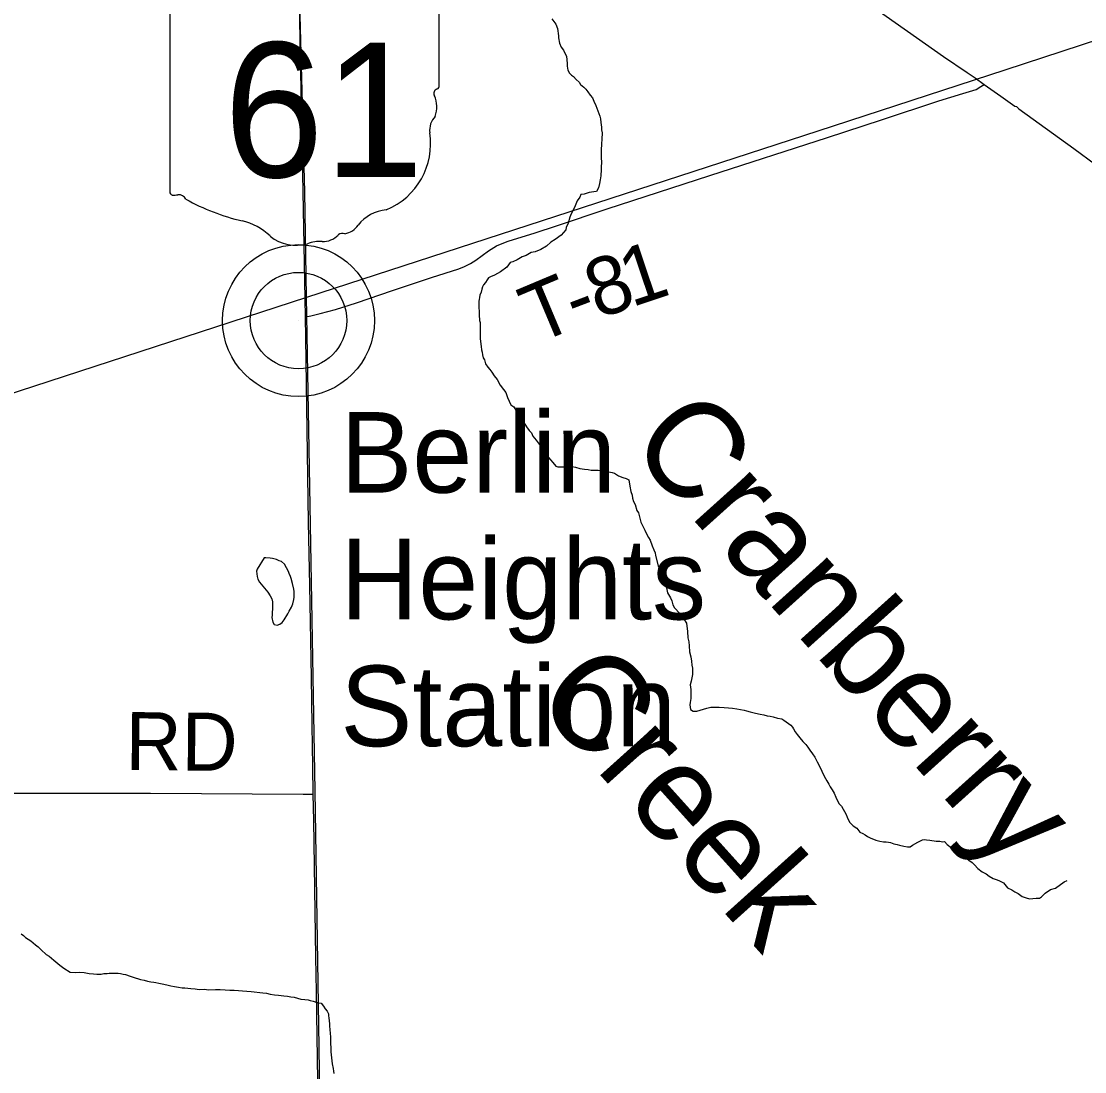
# Model space of a CAD drawing. Extents: x 0 to 34, y 0 to 22.
# Drawn here: x 6.721 to 7.762, y 15.772 to 16.8 of the extents above; entities that cross this region are included whole.
import ezdxf

# ---------------------------------------------------------------- set-up
doc = ezdxf.new("R2010")
doc.units = 0
for name, color, linetype in [('GM_X_Minor_Lake', 7, 'Continuous'), ('GM_X_Minor_River', 7, 'Continuous'), ('GM_X_Minor_River_Text', 7, 'Continuous'), ('GM_X_Rail_Line', 7, 'Continuous'), ('GM_X_State_Location', 7, 'Continuous'), ('GM_X_State_Route', 7, 'Continuous'), ('GM_X_State_Shield', 7, 'Continuous'), ('GM_X_Township_Road', 7, 'Continuous'), ('GM_X_Township_Road_Text', 7, 'Continuous'), ('GM_X_Unincorporated', 7, 'Continuous'), ('GM_X_Unincorporated_Location', 7, 'Continuous'), ('GM_X_Unincorporated_Text', 7, 'Continuous')]:
    doc.layers.add(name, color=color, linetype=linetype)

msp = doc.modelspace()

# ---------------------------------------------------------------- linework, layer by layer
at = {"layer": 'GM_X_Minor_Lake'}
for points in [[(6.9588, 16.2751), (6.9517, 16.264), (6.9513, 16.2621), (6.9518, 16.2568), (6.9526, 16.2541), (6.9541, 16.2511), (6.9574, 16.2471)], [(6.9574, 16.2471), (6.9622, 16.2413), (6.9645, 16.2379), (6.9661, 16.2348), (6.9669, 16.2318), (6.9669, 16.2265), (6.9669, 16.2246), (6.9666, 16.2219), (6.9666, 16.2189), (6.9662, 16.2166), (6.967, 16.212), (6.9686, 16.2098), (6.9713, 16.209), (6.9739, 16.2102), (6.9762, 16.2117), (6.9781, 16.2144), (6.9818, 16.2202), (6.9833, 16.2229), (6.9855, 16.2267), (6.9866, 16.2301), (6.9877, 16.2343), (6.9881, 16.2366), (6.988, 16.2419), (6.9876, 16.2442), (6.9864, 16.2499), (6.9852, 16.2548), (6.9845, 16.2567), (6.9833, 16.2598), (6.9825, 16.2617), (6.9786, 16.2688), (6.9756, 16.2715), (6.9733, 16.2722), (6.9706, 16.2733), (6.9668, 16.2744), (6.9645, 16.2748), (6.9603, 16.2751), (6.9592, 16.2751), (6.9588, 16.2751)]]:
    msp.add_lwpolyline(points, dxfattribs=at)
at = {"layer": 'GM_X_Minor_River'}
for points in [[(7.2405, 16.8028), (7.2444, 16.7975), (7.2459, 16.7934), (7.2468, 16.7861), (7.2468, 16.7842), (7.248, 16.7789), (7.2495, 16.7751), (7.2519, 16.7721), (7.2534, 16.7687), (7.2546, 16.7661), (7.2554, 16.7592), (7.2554, 16.7565), (7.2559, 16.7527), (7.2578, 16.7497), (7.2597, 16.7478), (7.2616, 16.7463), (7.2643, 16.7433), (7.267, 16.7407), (7.2685, 16.7384), (7.2716, 16.7358), (7.2735, 16.7339), (7.2755, 16.7313), (7.2778, 16.7282), (7.2801, 16.7256), (7.2816, 16.7222), (7.2836, 16.718), (7.2875, 16.7074), (7.2879, 16.7048), (7.2883, 16.7013), (7.2891, 16.6968), (7.2891, 16.6941), (7.2895, 16.6911), (7.2892, 16.685), (7.2889, 16.6804), (7.2886, 16.6743), (7.2886, 16.6709), (7.2886, 16.6678), (7.2891, 16.6614), (7.2887, 16.6587), (7.2888, 16.6553), (7.2884, 16.6492), (7.2877, 16.645), (7.287, 16.6416), (7.2859, 16.6374), (7.284, 16.6336), (7.2814, 16.6335), (7.2768, 16.6327), (7.2719, 16.6311), (7.2689, 16.6307), (7.2677, 16.6281), (7.2651, 16.6246), (7.2625, 16.6181), (7.2592, 16.612), (7.2581, 16.6085), (7.2562, 16.6028), (7.2544, 16.5986), (7.254, 16.5963), (7.2495, 16.591), (7.2435, 16.5867), (7.2393, 16.584), (7.2352, 16.5801), (7.2295, 16.577), (7.2242, 16.5747), (7.22, 16.5739), (7.2151, 16.5712), (7.2113, 16.5696), (7.2064, 16.5669), (7.2022, 16.565), (7.1996, 16.5642), (7.1962, 16.5596), (7.1902, 16.5549), (7.1841, 16.5518), (7.1803, 16.5503), (7.1784, 16.5491), (7.1769, 16.5472), (7.1755, 16.5445), (7.1736, 16.5422), (7.1725, 16.5403), (7.1717, 16.538), (7.171, 16.535), (7.1699, 16.5323), (7.1695, 16.53), (7.1692, 16.5281), (7.1688, 16.5262), (7.1688, 16.5235), (7.1693, 16.5129), (7.1694, 16.5075), (7.1701, 16.5056), (7.1702, 16.5034), (7.1702, 16.5003), (7.1702, 16.4958), (7.1703, 16.4938), (7.1703, 16.4893), (7.1711, 16.4821), (7.1716, 16.4786), (7.172, 16.4764), (7.1724, 16.4737), (7.1731, 16.471), (7.1743, 16.4688), (7.1755, 16.465), (7.1778, 16.4616)], [(7.1778, 16.4616), (7.1797, 16.4593), (7.1817, 16.4567), (7.184, 16.4533), (7.1867, 16.4495), (7.1898, 16.4442), (7.1929, 16.4397), (7.1952, 16.437), (7.1971, 16.4321), (7.2002, 16.4249), (7.2033, 16.423), (7.2041, 16.4211), (7.206, 16.4177), (7.2083, 16.4151), (7.2102, 16.4117), (7.2129, 16.4075), (7.2156, 16.4034), (7.2183, 16.3996), (7.2203, 16.3973), (7.2218, 16.3943), (7.2249, 16.3902), (7.2288, 16.3849), (7.2311, 16.3811), (7.2372, 16.3732), (7.2392, 16.3709), (7.2415, 16.3683), (7.2442, 16.3649), (7.2464, 16.3641), (7.2518, 16.3642), (7.2556, 16.3642), (7.2598, 16.3643), (7.2636, 16.3639), (7.2678, 16.3624), (7.2723, 16.3617), (7.2761, 16.3614), (7.2788, 16.361), (7.2807, 16.3607), (7.2834, 16.3607), (7.2856, 16.3607), (7.2879, 16.3604), (7.2906, 16.3604), (7.2936, 16.36), (7.2963, 16.3593), (7.2993, 16.3586), (7.3016, 16.3579), (7.3058, 16.3552), (7.31, 16.3538), (7.3131, 16.3526), (7.3158, 16.3515), (7.3166, 16.3451), (7.3178, 16.3398), (7.319, 16.3363), (7.3194, 16.3333), (7.3202, 16.3303), (7.3221, 16.3272), (7.3237, 16.3212), (7.3252, 16.3189), (7.3276, 16.3098), (7.3299, 16.3053), (7.3315, 16.3022), (7.333, 16.2984), (7.335, 16.295), (7.3365, 16.2924), (7.3385, 16.2867), (7.3404, 16.2829), (7.3416, 16.2799), (7.342, 16.2772), (7.3444, 16.267), (7.3463, 16.2628), (7.3479, 16.2594), (7.349, 16.256), (7.3506, 16.2526), (7.3517, 16.2503), (7.3522, 16.2473), (7.3537, 16.2408), (7.3565, 16.2359), (7.358, 16.2329), (7.3588, 16.2291), (7.3604, 16.226), (7.3657, 16.2204), (7.368, 16.22), (7.3692, 16.2155), (7.3723, 16.2109), (7.3731, 16.203), (7.3736, 16.1965), (7.3744, 16.1927), (7.3748, 16.1889), (7.3752, 16.1828), (7.3764, 16.1779), (7.3772, 16.1737), (7.3776, 16.1699), (7.3781, 16.1669), (7.3781, 16.1608), (7.3767, 16.1543), (7.3759, 16.1505), (7.3764, 16.1459), (7.3764, 16.1372), (7.3757, 16.1334), (7.3754, 16.1311), (7.3762, 16.1265), (7.3789, 16.125)], [(7.3789, 16.125), (7.3823, 16.1247), (7.3921, 16.1278), (7.3959, 16.1286), (7.3997, 16.1287), (7.4043, 16.1287), (7.4092, 16.1284), (7.4134, 16.128), (7.4172, 16.1277), (7.4214, 16.127), (7.4252, 16.1266), (7.4286, 16.1259), (7.4309, 16.1252), (7.4347, 16.1241), (7.4397, 16.123), (7.4443, 16.1219), (7.4481, 16.1212), (7.4511, 16.1204), (7.4542, 16.1201), (7.4572, 16.1194), (7.4614, 16.1179), (7.4656, 16.1172), (7.4675, 16.116), (7.4721, 16.1127), (7.4744, 16.1112), (7.4759, 16.1093), (7.4771, 16.1074), (7.4787, 16.1047), (7.4806, 16.1021), (7.4833, 16.0987), (7.4863, 16.0953), (7.489, 16.0923), (7.491, 16.0897), (7.4929, 16.0866), (7.4956, 16.0832), (7.4979, 16.0798), (7.5002, 16.0753), (7.5029, 16.0704), (7.5049, 16.0662), (7.5072, 16.0613), (7.5095, 16.0567), (7.5115, 16.0533), (7.513, 16.0507), (7.515, 16.0477), (7.5169, 16.0446), (7.5184, 16.0405), (7.5215, 16.0344), (7.5239, 16.0318), (7.5285, 16.0235), (7.5297, 16.0212), (7.532, 16.0163), (7.5355, 16.0125), (7.5389, 16.0102), (7.542, 16.0065), (7.545, 16.005), (7.5473, 16.0039), (7.5496, 16.002), (7.5527, 16.0005), (7.5554, 15.9994), (7.5576, 15.9986), (7.5615, 15.9975), (7.5653, 15.9968), (7.5679, 15.9969), (7.5702, 15.9965), (7.5721, 15.9961), (7.5752, 15.995), (7.5786, 15.9943), (7.5809, 15.9936), (7.5851, 15.9925), (7.5885, 15.9921), (7.5912, 15.9921), (7.5934, 15.9937), (7.5987, 15.9964), (7.6033, 15.9987), (7.6055, 15.9991), (7.6074, 15.9988), (7.6105, 15.9984), (7.6166, 15.9977), (7.6204, 15.9974), (7.623, 15.997), (7.6249, 15.9971), (7.6276, 15.9944), (7.6318, 15.9911), (7.6372, 15.9881), (7.6487, 15.979), (7.6521, 15.9768), (7.6544, 15.9745), (7.6575, 15.9708), (7.6617, 15.9674), (7.6656, 15.9655), (7.6686, 15.9633), (7.6724, 15.961), (7.6766, 15.9596), (7.6789, 15.9588), (7.6827, 15.9566), (7.6866, 15.952), (7.6908, 15.9498), (7.6939, 15.9479), (7.6969, 15.9464), (7.7011, 15.9434), (7.7049, 15.942)], [(7.7049, 15.942), (7.708, 15.9412), (7.7114, 15.9413), (7.7148, 15.9417), (7.7179, 15.9417), (7.7198, 15.9429), (7.7235, 15.9467), (7.7288, 15.9502), (7.7337, 15.9514), (7.742, 15.9576), (7.7451, 15.9591)], [(6.7207, 15.9069), (6.723, 15.905), (6.725, 15.9032), (6.7276, 15.9017), (6.7303, 15.8998), (6.7326, 15.8979), (6.7349, 15.896), (6.7372, 15.8942), (6.7403, 15.8911), (6.7453, 15.8866), (6.748, 15.8848), (6.7526, 15.881), (6.7587, 15.8761), (6.7625, 15.8731), (6.7686, 15.8694), (6.7736, 15.869), (6.7778, 15.8691), (6.7823, 15.8688), (6.7873, 15.868), (6.7915, 15.8677), (6.7949, 15.8674), (6.7991, 15.8674), (6.8017, 15.8678), (6.8048, 15.8678), (6.807, 15.8683), (6.8089, 15.8683), (6.8112, 15.8683), (6.8135, 15.8683), (6.8158, 15.8683), (6.8181, 15.868), (6.8207, 15.8673), (6.823, 15.8669), (6.8276, 15.8654), (6.8303, 15.8643), (6.8375, 15.8621), (6.8413, 15.8614), (6.8444, 15.8606), (6.8478, 15.8599), (6.8505, 15.8596), (6.8527, 15.8592), (6.8554, 15.8585), (6.8588, 15.8578), (6.8634, 15.8567), (6.8672, 15.8559), (6.871, 15.8552), (6.8748, 15.8545), (6.8783, 15.8538), (6.8809, 15.8538), (6.884, 15.8535), (6.887, 15.8531), (6.8912, 15.8528), (6.895, 15.8524), (6.9, 15.8525), (6.9045, 15.8521), (6.911, 15.8522), (6.9155, 15.8523), (6.9205, 15.8519), (6.925, 15.8516), (6.9292, 15.8516), (6.9334, 15.8513), (6.9376, 15.851), (6.9418, 15.8506), (6.946, 15.8503), (6.9574, 15.8489), (6.9608, 15.8486), (6.9646, 15.8478), (6.9688, 15.8471), (6.9726, 15.8468), (6.9779, 15.8461), (6.9814, 15.8457), (6.9848, 15.845), (6.9882, 15.8447), (6.9913, 15.8439), (6.9947, 15.8428), (6.9985, 15.8425), (7.0016, 15.8421), (7.0038, 15.8414), (7.0065, 15.8407), (7.0096, 15.8399), (7.0122, 15.8392), (7.0145, 15.8388), (7.0168, 15.8358), (7.0184, 15.8332), (7.0203, 15.8309), (7.0215, 15.8286)], [(7.0215, 15.8286), (7.0215, 15.8264), (7.0219, 15.8245), (7.0227, 15.8188), (7.0227, 15.8165), (7.0231, 15.8131), (7.0232, 15.8092), (7.0236, 15.8058), (7.0236, 15.802), (7.0237, 15.799), (7.0241, 15.7956), (7.0241, 15.7914), (7.0245, 15.7853), (7.0254, 15.7796), (7.0262, 15.775), (7.0266, 15.7724), (7.027, 15.7701)]]:
    msp.add_lwpolyline(points, dxfattribs=at)
at = {"layer": 'GM_X_Rail_Line'}
for points in [[(7.0001, 16.5307), (6.9984, 16.6334), (6.9864, 17.0905), (6.98, 17.5697), (6.9695, 17.6243), (6.954, 17.6886), (6.9362, 17.7597), (6.9253, 17.8041)], [(4.7274, 15.7912), (4.9149, 15.8505), (5.235, 15.9568), (5.5432, 16.0566), (5.6906, 16.1019), (6.056, 16.2214), (6.3367, 16.3138), (6.6888, 16.4288), (7.0003, 16.5302), (7.5012, 16.6931), (7.6844, 16.7528), (7.8339, 16.8018), (7.9505, 16.8406), (8.0234, 16.8694), (8.0878, 16.9029), (8.1469, 16.9344), (8.2358, 16.9935), (8.3923, 17.1058), (8.5744, 17.2368), (8.7463, 17.3593), (8.8719, 17.4493), (8.9, 17.4694)], [(6.9864, 14.5814), (6.9881, 14.7854), (7.0056, 14.912), (7.0171, 14.9895), (7.0235, 15.125), (7.0175, 15.4278), (7.0124, 15.7959), (7.0086, 16.0468), (7.0001, 16.5307)]]:
    msp.add_lwpolyline(points, dxfattribs=at)
at = {"layer": 'GM_X_State_Route'}
msp.add_lwpolyline([(7.0112, 15.7629), (7.0099, 15.8499), (7.0092, 15.8841), (7.0072, 16.0178), (7.0067, 16.0436), (7.0062, 16.0706), (7.0057, 16.111), (7.005, 16.1577), (7.0034, 16.2478), (7.0022, 16.31), (6.9994, 16.4903), (6.9991, 16.511), (6.9959, 16.6861), (6.994, 16.7825), (6.9927, 16.8602)], dxfattribs=at)
at = {"layer": 'GM_X_State_Shield'}
for p, q in [((7.13, 16.7375), (7.13, 16.8422)), ((6.8663, 16.8338), (6.8663, 16.6337)), ((7.13, 16.7375), (7.13, 16.7375))]:
    msp.add_line(p, q, dxfattribs=at)
for centre, radius, start, end in [((7.1269, 16.7371), 0.00314, 289.6038, 7.7341), ((7.1293, 16.7298), 0.00454, 107.944, 210.337), ((7.1004, 16.7166), 0.0273, 340.033, 23.6496), ((7.1405, 16.6937), 0.0198, 136.8065, 186.9296), ((7.0517, 16.6804), 0.0699, 292.3089, 8.9858), ((6.8694, 16.6332), 0.00308, 171.9584, 258.3066), ((6.8698, 16.6537), 0.0235, 267.339, 280.6039), ((6.8747, 16.6221), 0.00848, 29.7484, 93.2717), ((6.9817, 16.8019), 0.2019, 240.4129, 257.1985), ((7.0812, 16.5775), 0.0383, 94.4031, 142.5768), ((6.9215, 16.5438), 0.0632, 47.1842, 75.836), ((7.0327, 16.6143), 0.0226, 282.8732, 323.2771), ((6.9898, 16.6211), 0.0401, 230.7004, 286.2918), ((7.0159, 16.6061), 0.0214, 268.777, 315.5493), ((7.0353, 16.5868), 0.00601, 65.7517, 132.6484), ((7.013, 16.5519), 0.0329, 85.6951, 111.2099)]:
    msp.add_arc(centre, radius, start, end, dxfattribs=at)
at = {"layer": 'GM_X_Township_Road'}
for points in [[(7.5501, 16.8177), (7.6239, 16.7659), (7.6471, 16.7503), (7.6548, 16.7451), (7.6636, 16.7386)], [(6.9991, 16.511), (7.0044, 16.5121), (7.0134, 16.5141), (7.0284, 16.5182), (7.0492, 16.5248), (7.0843, 16.5369), (7.1226, 16.5494), (7.1492, 16.558), (7.155, 16.5604), (7.1606, 16.5632), (7.1659, 16.5666), (7.1784, 16.5757), (7.1835, 16.579), (7.1862, 16.5805), (7.1918, 16.5829), (7.1976, 16.585), (7.2242, 16.5934), (7.2448, 16.6), (7.2947, 16.6168), (7.3449, 16.633), (7.395, 16.6495), (7.5102, 16.6866), (7.5632, 16.704), (7.6192, 16.7224), (7.6429, 16.7297), (7.6558, 16.7336), (7.6604, 16.7366), (7.6636, 16.7386)], [(7.6636, 16.7386), (7.6799, 16.7272), (7.6938, 16.7173), (7.6954, 16.7169), (7.6976, 16.7148), (7.7514, 16.6757), (7.794, 16.6445)], [(6.0924, 16.0464), (6.1013, 16.0464), (6.123, 16.0466), (6.2692, 16.0456), (6.3407, 16.0453), (6.462, 16.0452), (6.5428, 16.0454), (6.6143, 16.0446), (6.6764, 16.0447), (6.8475, 16.0444), (6.9967, 16.0437), (7.0067, 16.0436)]]:
    msp.add_lwpolyline(points, dxfattribs=at)
at = {"layer": 'GM_X_Unincorporated'}
for radius in [0.0744, 0.0472]:
    msp.add_circle((6.9923, 16.5073), radius, dxfattribs=at)
at = {"layer": 'GM_X_Unincorporated_Location'}
msp.add_line((6.9923, 16.5073), (6.9923, 16.5073), dxfattribs=at)

# ---------------------------------------------------------------- texts
at = {"layer": 'GM_X_Minor_River_Text'}
for s, rotation, p in [('Cranberry', 311.9986, (7.3133, 16.3848)), ('Creek', 311.9987, (7.2207, 16.1366))]:
    msp.add_text(s, height=0.09475, rotation=rotation, dxfattribs=at).set_placement(p)
at = {"layer": 'GM_X_State_Location'}
for s in ['s', 'r']:
    msp.add_text(s, height=0.000189, dxfattribs=at).set_placement((6.9952, 16.7204))
msp.add_text('61', height=0.000189, rotation=0, dxfattribs=at).set_placement((6.9475, 16.7066))
at = {"layer": 'GM_X_State_Shield'}
msp.add_text('61', height=0.13184, dxfattribs=at).set_placement((6.919, 16.6478))
at = {"layer": 'GM_X_Township_Road_Text'}
for s, height, rotation, p in [('1', 0.0568, 18.5164, (7.3183, 16.5201)), ('8', 0.0568, 19.5425, (7.2856, 16.5085)), ('T', 0.0568, 22.8193, (7.2254, 16.484)), ('-', 0.0568, 20.9041, (7.2641, 16.5003)), ('RD', 0.05682, 359.5117, (6.8227, 16.0672))]:
    msp.add_text(s, height=height, rotation=rotation, dxfattribs=at).set_placement(p)
at = {"layer": 'GM_X_Unincorporated_Text'}
for s, p in [('Berlin', (7.0333, 16.3388)), ('Heights', (7.0333, 16.2147)), ('Station', (7.0333, 16.0905))]:
    msp.add_text(s, height=0.07898, rotation=0, dxfattribs=at).set_placement(p)

doc.saveas('drawing.dxf')
